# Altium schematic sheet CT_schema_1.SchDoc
size 404 x 338 mm
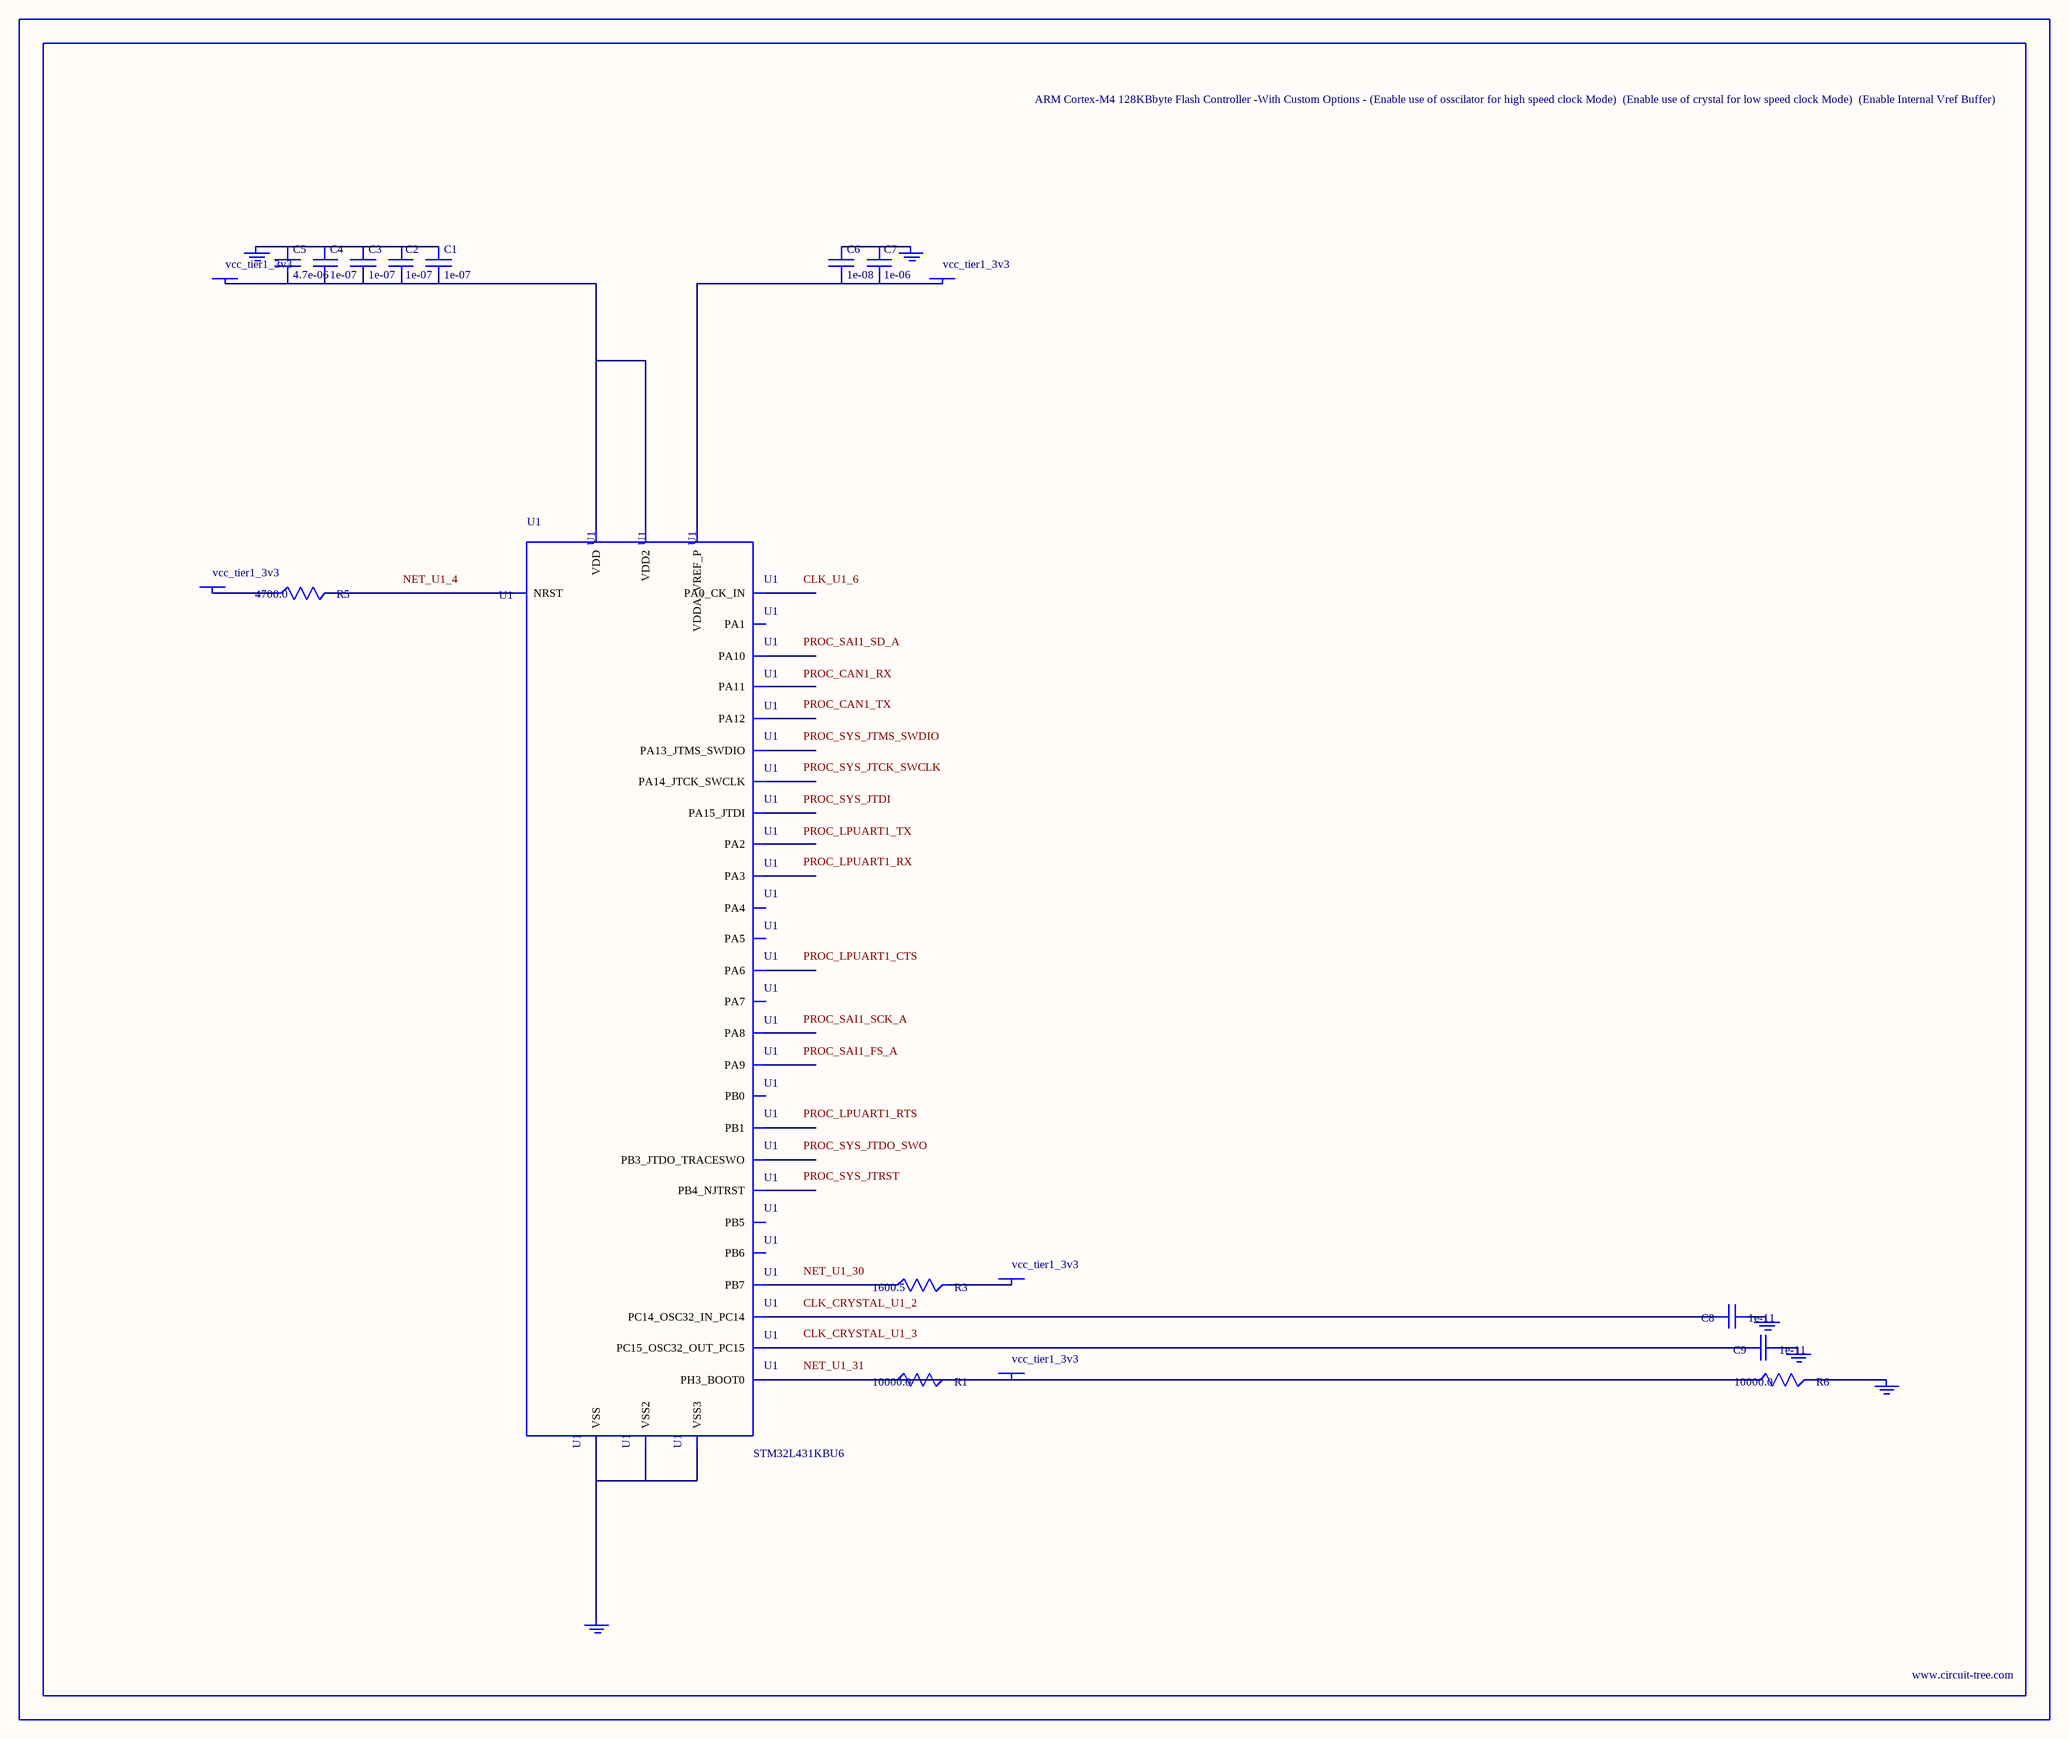
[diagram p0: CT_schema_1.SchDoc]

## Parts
BORDER0  (no value)
C1  1e-07  [C0603]
C2  1e-07  [C0603]
C3  1e-07  [C0603]
C4  1e-07  [C0603]
C5  4.7e-06  [C0603]
C6  1e-08  [C0603]
C7  1e-06  [C0603]
C8  1e-11  [C0402]
C9  1e-11  [C0402]
GND_INSTANCE_0_0  (no value)
GND_INSTANCE_0_1  (no value)
GND_INSTANCE_0_2  (no value)
GND_INSTANCE_0_3  (no value)
GND_INSTANCE_0_4  (no value)
GND_INSTANCE_0_5  (no value)
POWER_INSTANCE_0_0  vcc_tier1_3v3
POWER_INSTANCE_0_1  vcc_tier1_3v3
POWER_INSTANCE_0_2  vcc_tier1_3v3
POWER_INSTANCE_0_3  vcc_tier1_3v3
POWER_INSTANCE_0_4  vcc_tier1_3v3
R1  10000.0  [R0603]
R3  1600.5  [R0603]
R5  4700.0  [R0603]
R6  10000.0  [R0603]
U1  STM32L431KBU6  [QFN-32]

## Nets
NetC1_1: C1.1 C2.1 C3.1 C4.1 C5.1 GND_INSTANCE_0_0.0(GND)
NetC1_2: C1.2 C2.2 C3.2 C4.2 C5.2 POWER_INSTANCE_0_0.0(PWR) U1.1(VDD) U1.17(VDD2)
NetC6_1: C6.1 C7.1 GND_INSTANCE_0_3.0(GND)
NetC6_2: C6.2 C7.2 POWER_INSTANCE_0_1.0(PWR) U1.5(VDDA_VREF_P)
NetC8_1: C8.1 GND_INSTANCE_0_1.0(GND)
NetC8_2: C8.2 U1.2(PC14_OSC32_IN_PC14)
NetC9_1: C9.1 GND_INSTANCE_0_2.0(GND)
NetC9_2: C9.2 U1.3(PC15_OSC32_OUT_PC15)
NetGND_INSTANCE_0_4_0: GND_INSTANCE_0_4.0(GND) R6.2
NetGND_INSTANCE_0_5_0: GND_INSTANCE_0_5.0(GND) U1.16(VSS) U1.32(VSS2) U1.EXP(VSS3)
NetPOWER_INSTANCE_0_2_0: POWER_INSTANCE_0_2.0(PWR) R5.1
NetPOWER_INSTANCE_0_3_0: POWER_INSTANCE_0_3.0(PWR) R3.2
NetPOWER_INSTANCE_0_4_0: POWER_INSTANCE_0_4.0(PWR) R1.1 R1.2 R6.1 U1.31(PH3_BOOT0)
NetR3_1: R3.1 U1.30(PB7)
NetR5_2: R5.2 U1.4(NRST)

Not connected (* = marked no-connect by the designer): U1 6(PA0_CK_IN) 7(PA1) 8(PA2) 9(PA3) 10(PA4) 11(PA5) 12(PA6) 13(PA7) 14(PB0) 15(PB1) 18(PA8) 19(PA9) 20(PA10) 21(PA11) 22(PA12) 23(PA13_JTMS_SWDIO) 24(PA14_JTCK_SWCLK) 25(PA15_JTDI) 26(PB3_JTDO_TRACESWO) 27(PB4_NJTRST) 28(PB5) 29(PB6)

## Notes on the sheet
- Labels drawn without touching a wire or pin: CLK_CRYSTAL_U1_2, CLK_CRYSTAL_U1_3, CLK_U1_6, NET_U1_4, NET_U1_30, NET_U1_31, PROC_CAN1_RX, PROC_CAN1_TX, PROC_LPUART1_CTS, PROC_LPUART1_RTS, PROC_LPUART1_RX, PROC_LPUART1_TX, PROC_SAI1_FS_A, PROC_SAI1_SCK_A, PROC_SAI1_SD_A, PROC_SYS_JTCK_SWCLK, PROC_SYS_JTDI, PROC_SYS_JTDO_SWO, PROC_SYS_JTMS_SWDIO, PROC_SYS_JTRST

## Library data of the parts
BORDER0 = BORDER_PAGE0
C1-C4 = 06035C104K4Z2A
C5 = GRM188R6YA475KE15D
C6 = 06035C103K4Z2A
C7 = C0603C105K3RACTU
C8 C9 = C0402C100K3GACTU
GND_INSTANCE_0_0-GND_INSTANCE_0_5 = GND
POWER_INSTANCE_0_0-POWER_INSTANCE_0_4 = PWR
R1 R6 = RC0603JR-0710KL
R3 = R3
R5 = RC0603JR-074K7L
